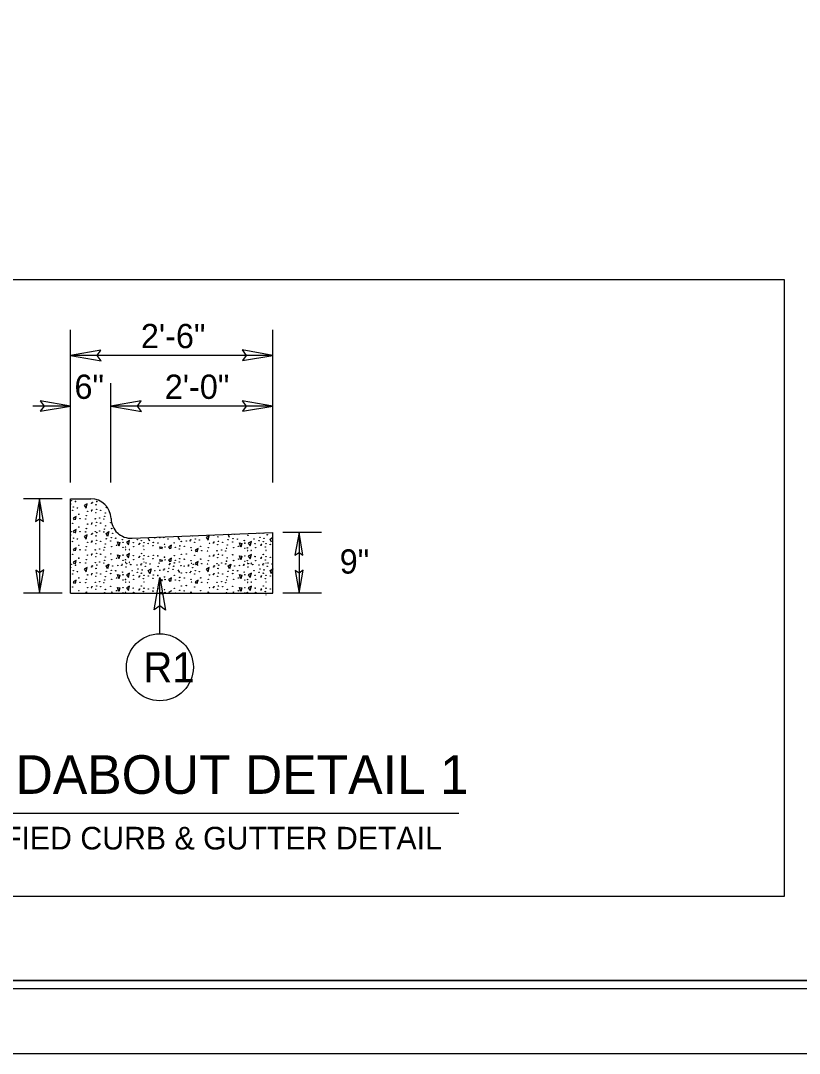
# Model space of a CAD drawing. Extents: x 1640342 to 1730599, y 538663 to 843747.
# Drawn here: x 1729959.6 to 1730007.8, y 538663.2 to 538727.1 of the extents above; entities that cross this region are included whole.
import ezdxf

# ---------------------------------------------------------------- set-up
doc = ezdxf.new("R2010")
doc.units = 0
for name, color, linetype in [('Default', 7, 'Continuous'), ('Sheet Plan CELL', 7, 'Continuous'), ('Sheet Plot Border Inside CELL', 7, 'Continuous'), ('Sheet Plot Border Outside CELL', 7, 'Continuous'), ('Typical Curb CELL', 7, 'Continuous'), ('Typical ID Circle CELL', 7, 'Continuous'), ('Typical Pavement Slope CELL', 7, 'Continuous'), ('Typical Terminator CELL', 7, 'Continuous'), ('Typical Text ID Circle CELL', 7, 'Continuous'), ('Typical Text Label CELL', 7, 'Continuous')]:
    doc.layers.add(name, color=color, linetype=linetype)

msp = doc.modelspace()

# ---------------------------------------------------------------- linework, layer by layer
at = {"layer": 'Default'}
for p, q in [((1729962.679, 538698.511), (1729962.679, 538707.96)), ((1729975.179, 538698.511), (1729975.179, 538707.96)), ((1729975.179, 538706.377), (1729962.679, 538706.377)), ((1729965.173, 538698.511), (1729965.173, 538704.667)), ((1729962.679, 538703.241), (1729960.338, 538703.241)), ((1729975.179, 538703.241), (1729965.173, 538703.241)), ((1729962.15, 538697.511), (1729959.761, 538697.511)), ((1729960.761, 538697.511), (1729960.761, 538691.677)), ((1729978.196, 538695.427), (1729975.807, 538695.427)), ((1729976.807, 538695.427), (1729976.807, 538691.677)), ((1729962.15, 538691.677), (1729959.761, 538691.677)), ((1729978.196, 538691.677), (1729975.807, 538691.677))]:
    msp.add_line(p, q, dxfattribs=at)
for points in [[(1729964.553, 538706.699), (1729962.679, 538706.377), (1729964.564, 538706.043), (1729964.324, 538706.377)], [(1729973.305, 538706.054), (1729975.179, 538706.377), (1729973.295, 538706.71), (1729973.534, 538706.377)], [(1729960.805, 538702.918), (1729962.679, 538703.241), (1729960.795, 538703.574), (1729961.034, 538703.241)], [(1729967.047, 538703.563), (1729965.173, 538703.241), (1729967.057, 538702.907), (1729966.818, 538703.241)], [(1729973.305, 538702.918), (1729975.179, 538703.241), (1729973.295, 538703.574), (1729973.534, 538703.241)], [(1729961.003, 538696.105), (1729960.761, 538697.511), (1729960.511, 538696.098), (1729960.761, 538696.277)], [(1729977.049, 538694.022), (1729976.807, 538695.427), (1729976.557, 538694.014), (1729976.807, 538694.194)], [(1729960.522, 538693.099), (1729960.764, 538691.693), (1729961.014, 538693.106), (1729960.764, 538692.927)], [(1729976.565, 538693.078), (1729976.807, 538691.672), (1729977.057, 538693.086), (1729976.807, 538692.906)]]:
    msp.add_lwpolyline(points, close=True, dxfattribs=at)
at = {"layer": 'Sheet Plan CELL'}
for points in [[(1729873.99, 538667.718), (1729873.985, 538877.713), (1730133.983, 538877.721), (1730133.985, 538847.708), (1730173.993, 538847.706), (1730173.993, 538667.718)], [(1730173.998, 538877.718), (1729873.99, 538877.718), (1729873.99, 538667.718), (1730173.993, 538667.718)]]:
    msp.add_lwpolyline(points, close=True, dxfattribs=at)
at = {"layer": 'Sheet Plot Border Inside CELL'}
msp.add_lwpolyline([(1729843.293, 538667.216), (1730176.49, 538667.218), (1730176.493, 538878.216), (1729843.293, 538878.216)], close=True, dxfattribs=at)
at = {"layer": 'Sheet Plot Border Outside CELL'}
msp.add_lwpolyline([(1729840.693, 538663.216), (1730177.393, 538663.216), (1730177.393, 538882.216), (1729840.693, 538882.216)], close=True, dxfattribs=at)
at = {"layer": 'Typical Curb CELL'}
for p, q in [((1729963.704, 538697.2), (1729963.518, 538697.097)), ((1729963.518, 538697.097), (1729963.638, 538696.929)), ((1729963.638, 538696.929), (1729963.704, 538697.2)), ((1729963.02, 538696.405), (1729962.834, 538696.303)), ((1729962.834, 538696.303), (1729962.901, 538696.209)), ((1729962.973, 538696.211), (1729963.02, 538696.405)), ((1729963.02, 538695.607), (1729962.834, 538695.505)), ((1729962.834, 538695.505), (1729962.901, 538695.411)), ((1729962.973, 538695.412), (1729963.02, 538695.607)), ((1729963.704, 538695.279), (1729963.518, 538695.177)), ((1729963.518, 538695.177), (1729963.638, 538695.009)), ((1729963.638, 538695.009), (1729963.704, 538695.279)), ((1729964.882, 538695.371), (1729965.052, 538695.492)), ((1729964.966, 538695.184), (1729964.882, 538695.371)), ((1729965.052, 538695.492), (1729964.966, 538695.184)), ((1729967.57, 538694.893), (1729967.486, 538695.079)), ((1729969.302, 538695.13), (1729969.423, 538694.962)), ((1729971.244, 538695.22), (1729971.057, 538695.118)), ((1729971.057, 538695.118), (1729971.178, 538694.95)), ((1729971.178, 538694.95), (1729971.244, 538695.22)), ((1729972.505, 538695.125), (1729972.421, 538695.312)), ((1729975.026, 538695.02), (1729975.196, 538695.141)), ((1729975.11, 538694.834), (1729975.026, 538695.02)), ((1729963.02, 538694.485), (1729962.834, 538694.382)), ((1729962.834, 538694.382), (1729962.901, 538694.289)), ((1729962.973, 538694.29), (1729963.02, 538694.485)), ((1729965.584, 538694.838), (1729965.734, 538694.809)), ((1729965.658, 538694.584), (1729965.584, 538694.838)), ((1729965.734, 538694.809), (1729965.658, 538694.584)), ((1729966.088, 538694.355), (1729966.095, 538694.355)), ((1729966.318, 538694.926), (1729966.132, 538694.824)), ((1729966.132, 538694.824), (1729966.253, 538694.656)), ((1729966.253, 538694.656), (1729966.318, 538694.926)), ((1729966.299, 538694.359), (1729966.32, 538694.36)), ((1729967.213, 538694.378), (1729967.235, 538694.379)), ((1729968.189, 538694.547), (1729968.338, 538694.518)), ((1729968.231, 538694.4), (1729968.189, 538694.547)), ((1729968.338, 538694.518), (1729968.299, 538694.401)), ((1729968.922, 538694.635), (1729968.736, 538694.532)), ((1729968.736, 538694.532), (1729968.822, 538694.412)), ((1729968.868, 538694.413), (1729968.922, 538694.635)), ((1729970.56, 538694.426), (1729970.373, 538694.323)), ((1729970.513, 538694.231), (1729970.56, 538694.426)), ((1729973.124, 538694.779), (1729973.274, 538694.75)), ((1729973.198, 538694.525), (1729973.124, 538694.779)), ((1729973.274, 538694.75), (1729973.198, 538694.525)), ((1729973.858, 538694.867), (1729973.671, 538694.765)), ((1729973.671, 538694.765), (1729973.792, 538694.597)), ((1729973.792, 538694.597), (1729973.858, 538694.867)), ((1729965.584, 538694.04), (1729965.734, 538694.011)), ((1729965.658, 538693.786), (1729965.584, 538694.04)), ((1729965.734, 538694.011), (1729965.658, 538693.786)), ((1729966.318, 538694.128), (1729966.132, 538694.026)), ((1729966.132, 538694.026), (1729966.253, 538693.858)), ((1729966.253, 538693.858), (1729966.318, 538694.128)), ((1729968.189, 538693.749), (1729968.338, 538693.72)), ((1729968.231, 538693.601), (1729968.189, 538693.749)), ((1729968.338, 538693.72), (1729968.299, 538693.603)), ((1729968.922, 538693.837), (1729968.736, 538693.734)), ((1729968.736, 538693.734), (1729968.822, 538693.614)), ((1729968.868, 538693.615), (1729968.922, 538693.837)), ((1729970.373, 538694.323), (1729970.441, 538694.229)), ((1729973.124, 538693.981), (1729973.274, 538693.952)), ((1729973.198, 538693.727), (1729973.124, 538693.981)), ((1729973.274, 538693.952), (1729973.198, 538693.727)), ((1729973.627, 538694.296), (1729973.635, 538694.296)), ((1729973.858, 538694.069), (1729973.671, 538693.966)), ((1729973.671, 538693.966), (1729973.792, 538693.798)), ((1729973.792, 538693.798), (1729973.858, 538694.069)), ((1729973.839, 538694.3), (1729973.86, 538694.301)), ((1729974.753, 538694.319), (1729974.775, 538694.32)), ((1729963.02, 538693.687), (1729962.834, 538693.584)), ((1729962.834, 538693.584), (1729962.901, 538693.49)), ((1729962.973, 538693.492), (1729963.02, 538693.687)), ((1729963.704, 538693.264), (1729963.518, 538693.161)), ((1729963.518, 538693.161), (1729963.638, 538692.993)), ((1729963.638, 538692.993), (1729963.704, 538693.264)), ((1729964.882, 538693.355), (1729965.052, 538693.476)), ((1729964.966, 538693.169), (1729964.882, 538693.355)), ((1729965.052, 538693.476), (1729964.966, 538693.169)), ((1729966.088, 538693.557), (1729966.095, 538693.557)), ((1729966.299, 538693.561), (1729966.32, 538693.562)), ((1729967.213, 538693.58), (1729967.235, 538693.581)), ((1729967.486, 538693.064), (1729967.656, 538693.185)), ((1729967.656, 538693.185), (1729967.57, 538692.877)), ((1729969.302, 538693.114), (1729969.423, 538692.946)), ((1729970.56, 538693.627), (1729970.373, 538693.525)), ((1729970.373, 538693.525), (1729970.441, 538693.431)), ((1729970.513, 538693.433), (1729970.56, 538693.627)), ((1729971.244, 538693.264), (1729971.057, 538693.161)), ((1729971.057, 538693.161), (1729971.178, 538692.993)), ((1729971.178, 538692.993), (1729971.244, 538693.264)), ((1729972.421, 538693.355), (1729972.591, 538693.476)), ((1729972.505, 538693.169), (1729972.421, 538693.355)), ((1729972.591, 538693.476), (1729972.505, 538693.169)), ((1729973.627, 538693.498), (1729973.635, 538693.498)), ((1729973.839, 538693.502), (1729973.86, 538693.503)), ((1729974.753, 538693.521), (1729974.775, 538693.522)), ((1729975.026, 538693.064), (1729975.196, 538693.185)), ((1729975.196, 538693.185), (1729975.11, 538692.877)), ((1729963.02, 538692.469), (1729962.834, 538692.367)), ((1729962.973, 538692.275), (1729963.02, 538692.469)), ((1729965.584, 538692.823), (1729965.734, 538692.794)), ((1729965.658, 538692.569), (1729965.584, 538692.823)), ((1729965.734, 538692.794), (1729965.658, 538692.569)), ((1729966.318, 538692.911), (1729966.132, 538692.808)), ((1729966.132, 538692.808), (1729966.253, 538692.64)), ((1729966.253, 538692.64), (1729966.318, 538692.911)), ((1729967.57, 538692.877), (1729967.486, 538693.064)), ((1729968.189, 538692.531), (1729968.338, 538692.502)), ((1729968.231, 538692.384), (1729968.189, 538692.531)), ((1729968.338, 538692.502), (1729968.299, 538692.386)), ((1729968.922, 538692.619), (1729968.736, 538692.517)), ((1729968.736, 538692.517), (1729968.822, 538692.396)), ((1729968.868, 538692.397), (1729968.922, 538692.619)), ((1729970.56, 538692.469), (1729970.373, 538692.367)), ((1729970.513, 538692.275), (1729970.56, 538692.469)), ((1729973.124, 538692.823), (1729973.274, 538692.794)), ((1729973.198, 538692.569), (1729973.124, 538692.823)), ((1729973.274, 538692.794), (1729973.198, 538692.569)), ((1729973.858, 538692.911), (1729973.671, 538692.808)), ((1729973.671, 538692.808), (1729973.792, 538692.64)), ((1729973.792, 538692.64), (1729973.858, 538692.911)), ((1729975.11, 538692.877), (1729975.026, 538693.064)), ((1729962.834, 538692.367), (1729962.901, 538692.273)), ((1729965.584, 538692.024), (1729965.734, 538691.996)), ((1729965.658, 538691.77), (1729965.584, 538692.024)), ((1729965.734, 538691.996), (1729965.658, 538691.77)), ((1729966.088, 538692.339), (1729966.095, 538692.34)), ((1729966.318, 538692.113), (1729966.132, 538692.01)), ((1729966.132, 538692.01), (1729966.253, 538691.842)), ((1729966.253, 538691.842), (1729966.318, 538692.113)), ((1729966.299, 538692.344), (1729966.32, 538692.344)), ((1729967.213, 538692.363), (1729967.235, 538692.363)), ((1729968.922, 538691.821), (1729968.736, 538691.719)), ((1729970.373, 538692.367), (1729970.441, 538692.273)), ((1729973.124, 538692.024), (1729973.274, 538691.996)), ((1729973.198, 538691.77), (1729973.124, 538692.024)), ((1729973.274, 538691.996), (1729973.198, 538691.77)), ((1729973.627, 538692.339), (1729973.635, 538692.34)), ((1729973.858, 538692.113), (1729973.671, 538692.01)), ((1729973.671, 538692.01), (1729973.792, 538691.842)), ((1729973.792, 538691.842), (1729973.858, 538692.113)), ((1729973.839, 538692.344), (1729973.86, 538692.344)), ((1729974.753, 538692.363), (1729974.775, 538692.363)), ((1729968.189, 538691.733), (1729968.338, 538691.704)), ((1729968.231, 538691.586), (1729968.189, 538691.733)), ((1729968.338, 538691.704), (1729968.299, 538691.587)), ((1729974.753, 538691.565), (1729974.775, 538691.565))]:
    msp.add_line(p, q, dxfattribs=at)
for centre in [(1729962.682, 538697.19), (1729962.729, 538697.395), (1729962.852, 538696.994), (1729962.982, 538697.34), (1729963.104, 538696.938), (1729963.989, 538697.235), (1729964.021, 538697.295), (1729964.255, 538697.136), (1729964.302, 538697.342), (1729964.882, 538696.954), (1729962.805, 538696.788), (1729963.188, 538696.555), (1729963.254, 538696.274), (1729963.606, 538696.261), (1729963.652, 538696.467), (1729963.729, 538696.74), (1729963.972, 538696.75), (1729964.005, 538696.81), (1729964.201, 538696.271), (1729964.239, 538696.651), (1729964.286, 538696.857), (1729964.482, 538696.318), (1729964.538, 538696.801), (1729964.734, 538696.262), (1729964.781, 538696.429), (1729964.827, 538696.635), (1729962.805, 538695.99), (1729963.188, 538695.756), (1729963.652, 538695.669), (1729963.729, 538695.942), (1729963.972, 538695.951), (1729964.005, 538696.012), (1729964.239, 538695.853), (1729964.286, 538696.059), (1729964.538, 538696.003), (1729964.781, 538695.631), (1729964.827, 538695.836), (1729965.163, 538696.025), (1729965.219, 538695.67), (1729962.682, 538695.269), (1729962.729, 538695.475), (1729962.852, 538695.074), (1729962.982, 538695.419), (1729963.104, 538695.018), (1729963.254, 538695.476), (1729963.606, 538695.463), (1729963.989, 538695.315), (1729964.021, 538695.375), (1729964.201, 538695.473), (1729964.255, 538695.216), (1729964.302, 538695.422), (1729964.482, 538695.52), (1729964.734, 538695.464), (1729964.882, 538695.034), (1729965.191, 538695.099), (1729965.284, 538695.371), (1729965.472, 538695.071), (1729965.593, 538695.399), (1729965.883, 538694.987), (1729966.8, 538694.979), (1729967.889, 538695.079), (1729968.197, 538695.107), (1729968.44, 538695.117), (1729968.707, 538695.018), (1729970.222, 538695.21), (1729970.391, 538695.015), (1729971.529, 538695.256), (1729971.795, 538695.157), (1729972.73, 538695.04), (1729972.824, 538695.312), (1729973.011, 538695.012), (1729973.643, 538695.25), (1729974.026, 538695.016), (1729974.329, 538695.37), (1729974.386, 538695.126), (1729974.572, 538695.38), (1729974.643, 538695.07), (1729974.838, 538695.281), (1729962.805, 538694.868), (1729963.188, 538694.634), (1729963.254, 538694.354), (1729963.606, 538694.34), (1729963.652, 538694.546), (1729963.729, 538694.82), (1729963.972, 538694.829), (1729964.005, 538694.89), (1729964.201, 538694.351), (1729964.239, 538694.73), (1729964.286, 538694.936), (1729964.482, 538694.397), (1729964.538, 538694.88), (1729964.734, 538694.342), (1729964.781, 538694.508), (1729964.827, 538694.714), (1729965.163, 538694.903), (1729965.219, 538694.547), (1729965.518, 538694.631), (1729965.916, 538694.823), (1729965.916, 538694.505), (1729966.075, 538694.533), (1729966.552, 538694.795), (1729966.58, 538694.543), (1729966.911, 538694.685), (1729966.944, 538694.746), (1729967.057, 538694.923), (1729967.178, 538694.586), (1729967.224, 538694.792), (1729967.486, 538694.743), (1729967.767, 538694.611), (1729967.795, 538694.808), (1729968.076, 538694.78), (1729968.487, 538694.696), (1729968.52, 538694.532), (1729969.091, 538694.784), (1729969.156, 538694.504), (1729969.404, 538694.402), (1729969.432, 538694.599), (1729969.526, 538694.87), (1729969.713, 538694.571), (1729969.835, 538694.898), (1729970.078, 538694.908), (1729970.11, 538694.968), (1729970.125, 538694.487), (1729970.345, 538694.809), (1729970.644, 538694.959), (1729970.728, 538694.575), (1729971.192, 538694.487), (1729971.269, 538694.761), (1729971.512, 538694.77), (1729971.545, 538694.83), (1729971.779, 538694.671), (1729971.825, 538694.877), (1729972.021, 538694.338), (1729972.078, 538694.821), (1729972.32, 538694.449), (1729972.367, 538694.655), (1729972.422, 538694.975), (1729972.703, 538694.844), (1729972.759, 538694.488), (1729973.058, 538694.572), (1729973.423, 538694.928), (1729973.455, 538694.764), (1729973.455, 538694.446), (1729973.614, 538694.474), (1729974.092, 538694.736), (1729974.12, 538694.483), (1729974.339, 538694.92), (1729974.451, 538694.626), (1729974.483, 538694.686), (1729974.597, 538694.864), (1729974.717, 538694.527), (1729974.764, 538694.733), (1729975.026, 538694.683), (1729962.805, 538694.07), (1729963.188, 538693.836), (1729963.652, 538693.748), (1729963.729, 538694.022), (1729963.972, 538694.031), (1729964.005, 538694.091), (1729964.239, 538693.932), (1729964.286, 538694.138), (1729964.538, 538694.082), (1729964.781, 538693.71), (1729964.827, 538693.916), (1729965.163, 538694.105), (1729965.219, 538693.749), (1729965.518, 538693.833), (1729965.916, 538694.025), (1729965.916, 538693.707), (1729966.075, 538693.735), (1729966.552, 538693.997), (1729966.58, 538693.744), (1729966.911, 538693.887), (1729966.944, 538693.947), (1729967.057, 538694.125), (1729967.178, 538693.788), (1729967.224, 538693.994), (1729967.486, 538693.944), (1729967.767, 538693.813), (1729967.795, 538694.01), (1729968.076, 538693.982), (1729968.487, 538693.898), (1729968.52, 538693.733), (1729969.091, 538693.986), (1729969.156, 538693.706), (1729969.432, 538693.801), (1729969.526, 538694.072), (1729969.713, 538693.773), (1729969.835, 538694.1), (1729970.157, 538694.322), (1729970.345, 538694.011), (1729970.728, 538693.777), (1729970.793, 538694.295), (1729971.145, 538694.281), (1729971.269, 538693.962), (1729971.512, 538693.972), (1729971.545, 538694.032), (1729971.74, 538694.292), (1729971.779, 538693.873), (1729971.825, 538694.079), (1729972.078, 538694.023), (1729972.274, 538694.282), (1729972.367, 538693.857), (1729972.703, 538694.045), (1729973.058, 538693.774), (1729973.455, 538693.966), (1729974.092, 538693.938), (1729974.451, 538693.828), (1729974.483, 538693.888), (1729974.597, 538694.066), (1729974.717, 538693.729), (1729974.764, 538693.935), (1729975.026, 538693.885), (1729962.682, 538693.254), (1729962.729, 538693.46), (1729962.982, 538693.404), (1729963.254, 538693.556), (1729963.606, 538693.542), (1729963.989, 538693.299), (1729964.021, 538693.36), (1729964.201, 538693.553), (1729964.255, 538693.2), (1729964.302, 538693.406), (1729964.482, 538693.599), (1729964.734, 538693.543), (1729965.191, 538693.084), (1729965.284, 538693.355), (1729965.593, 538693.383), (1729965.836, 538693.393), (1729965.869, 538693.453), (1729966.103, 538693.294), (1729966.15, 538693.5), (1729966.402, 538693.444), (1729966.789, 538693.414), (1729966.846, 538693.169), (1729967.032, 538693.424), (1729967.064, 538693.484), (1729967.104, 538693.113), (1729967.298, 538693.325), (1729967.345, 538693.531), (1729967.598, 538693.475), (1729967.889, 538693.064), (1729968.103, 538693.322), (1729968.15, 538693.528), (1729968.197, 538693.092), (1729968.44, 538693.101), (1729968.473, 538693.162), (1729968.754, 538693.208), (1729968.787, 538693.439), (1729968.82, 538693.499), (1729969.006, 538693.152), (1729969.054, 538693.34), (1729969.1, 538693.546), (1729969.404, 538693.604), (1729969.498, 538693.367), (1729969.712, 538693.343), (1729969.956, 538693.352), (1729969.988, 538693.413), (1729970.125, 538693.689), (1729970.157, 538693.524), (1729970.222, 538693.254), (1729970.269, 538693.46), (1729970.521, 538693.404), (1729970.793, 538693.496), (1729971.145, 538693.483), (1729971.192, 538693.689), (1729971.529, 538693.299), (1729971.561, 538693.36), (1729971.74, 538693.493), (1729971.795, 538693.2), (1729971.842, 538693.406), (1729972.021, 538693.54), (1729972.274, 538693.484), (1729972.32, 538693.651), (1729972.73, 538693.084), (1729972.759, 538693.69), (1729972.824, 538693.355), (1729973.133, 538693.383), (1729973.376, 538693.393), (1729973.408, 538693.453), (1729973.455, 538693.648), (1729973.614, 538693.676), (1729973.643, 538693.294), (1729973.689, 538693.5), (1729973.942, 538693.444), (1729974.12, 538693.685), (1729974.329, 538693.414), (1729974.386, 538693.169), (1729974.572, 538693.424), (1729974.604, 538693.484), (1729974.643, 538693.113), (1729974.838, 538693.325), (1729974.885, 538693.531), (1729975.137, 538693.475), (1729962.805, 538692.853), (1729962.852, 538693.058), (1729963.104, 538693.002), (1729963.188, 538692.619), (1729963.652, 538692.531), (1729963.729, 538692.804), (1729963.972, 538692.814), (1729964.005, 538692.874), (1729964.239, 538692.715), (1729964.286, 538692.921), (1729964.538, 538692.865), (1729964.781, 538692.493), (1729964.827, 538692.699), (1729964.882, 538693.019), (1729965.163, 538692.887), (1729965.219, 538692.532), (1729965.472, 538693.056), (1729965.518, 538692.616), (1729965.883, 538692.972), (1729965.916, 538692.808), (1729965.916, 538692.49), (1729966.075, 538692.518), (1729966.486, 538693.06), (1729966.552, 538692.78), (1729966.58, 538692.527), (1729966.8, 538692.964), (1729966.911, 538692.67), (1729966.944, 538692.73), (1729967.057, 538692.908), (1729967.178, 538692.571), (1729967.224, 538692.777), (1729967.486, 538692.727), (1729967.767, 538692.596), (1729967.795, 538692.793), (1729968.076, 538692.765), (1729968.487, 538692.68), (1729968.52, 538692.516), (1729968.707, 538693.003), (1729969.091, 538692.769), (1729969.156, 538692.488), (1729969.404, 538692.446), (1729969.432, 538692.643), (1729969.526, 538692.914), (1729969.713, 538692.615), (1729969.835, 538692.942), (1729970.078, 538692.951), (1729970.11, 538693.012), (1729970.125, 538692.53), (1729970.345, 538692.853), (1729970.391, 538693.058), (1729970.644, 538693.002), (1729970.728, 538692.619), (1729971.192, 538692.531), (1729971.269, 538692.804), (1729971.512, 538692.814), (1729971.545, 538692.874), (1729971.779, 538692.715), (1729971.825, 538692.921), (1729972.078, 538692.865), (1729972.32, 538692.493), (1729972.367, 538692.699), (1729972.422, 538693.019), (1729972.703, 538692.887), (1729972.759, 538692.532), (1729973.011, 538693.056), (1729973.058, 538692.616), (1729973.423, 538692.972), (1729973.455, 538692.808), (1729973.455, 538692.49), (1729973.614, 538692.518), (1729974.026, 538693.06), (1729974.092, 538692.78), (1729974.12, 538692.527), (1729974.339, 538692.964), (1729974.451, 538692.67), (1729974.483, 538692.73), (1729974.597, 538692.908), (1729974.717, 538692.571), (1729974.764, 538692.777), (1729975.026, 538692.727), (1729962.805, 538692.054), (1729963.188, 538691.821), (1729963.254, 538692.338), (1729963.606, 538692.325), (1729963.729, 538692.006), (1729963.972, 538692.016), (1729964.005, 538692.076), (1729964.201, 538692.335), (1729964.239, 538691.917), (1729964.286, 538692.123), (1729964.482, 538692.382), (1729964.538, 538692.067), (1729964.734, 538692.326), (1729964.827, 538691.901), (1729965.163, 538692.089), (1729965.518, 538691.818), (1729965.916, 538692.009), (1729966.552, 538691.981), (1729966.911, 538691.872), (1729966.944, 538691.932), (1729967.057, 538692.109), (1729967.224, 538691.979), (1729967.486, 538691.929), (1729967.767, 538691.798), (1729967.795, 538691.994), (1729968.076, 538691.966), (1729968.487, 538691.882), (1729969.091, 538691.971), (1729969.432, 538691.844), (1729969.526, 538692.116), (1729969.713, 538691.816), (1729969.835, 538692.144), (1729970.157, 538692.366), (1729970.345, 538692.054), (1729970.728, 538691.821), (1729970.793, 538692.338), (1729971.145, 538692.325), (1729971.269, 538692.006), (1729971.512, 538692.016), (1729971.545, 538692.076), (1729971.74, 538692.335), (1729971.779, 538691.917), (1729971.825, 538692.123), (1729972.021, 538692.382), (1729972.078, 538692.067), (1729972.274, 538692.326), (1729972.367, 538691.901), (1729972.703, 538692.089), (1729973.058, 538691.818), (1729973.455, 538692.009), (1729974.092, 538691.981), (1729974.451, 538691.872), (1729974.483, 538691.932), (1729974.597, 538692.109), (1729974.764, 538691.979), (1729975.026, 538691.929), (1729963.652, 538691.733), (1729964.781, 538691.695), (1729965.219, 538691.734), (1729965.916, 538691.691), (1729966.075, 538691.719), (1729966.58, 538691.729), (1729967.178, 538691.773), (1729968.52, 538691.718), (1729969.156, 538691.69), (1729970.125, 538691.732), (1729971.192, 538691.733), (1729972.32, 538691.695), (1729972.759, 538691.734), (1729973.455, 538691.691), (1729973.614, 538691.719), (1729974.12, 538691.729), (1729974.717, 538691.773)]:
    msp.add_circle(centre, 0.0131, dxfattribs=at)
for centre, start, end in [((1729966.091, 538694.368), 287.79478, 254.59053), ((1729966.309, 538694.368), 323.39792, 218.98739), ((1729967.224, 538694.371), 36.13839, 146.24692), ((1729973.631, 538694.308), 287.79478, 254.59053), ((1729973.849, 538694.308), 323.39792, 218.98739), ((1729974.764, 538694.312), 36.13839, 146.24692), ((1729966.091, 538693.57), 287.79478, 254.59053), ((1729966.309, 538693.57), 323.39792, 218.98739), ((1729967.224, 538693.573), 36.13839, 146.24692), ((1729973.631, 538693.51), 287.79478, 254.59053), ((1729973.849, 538693.51), 323.39792, 218.98739), ((1729974.764, 538693.514), 36.13839, 146.24692), ((1729966.091, 538692.352), 287.79478, 254.59053), ((1729966.309, 538692.352), 323.39792, 218.98739), ((1729967.224, 538692.356), 36.13839, 146.24692), ((1729973.631, 538692.352), 287.79478, 254.59053), ((1729973.849, 538692.352), 323.39792, 218.98739), ((1729974.764, 538692.356), 36.13839, 146.24692), ((1729974.764, 538691.557), 36.13839, 146.24692)]:
    msp.add_arc(centre, 0.0131, start, end, dxfattribs=at)
at = {"layer": 'Typical ID Circle CELL'}
msp.add_line((1729968.198, 538689.16), (1729968.198, 538692.645), dxfattribs=at)
msp.add_circle((1729968.199, 538687.089), 2.071, dxfattribs=at)
at = {"layer": 'Typical Pavement Slope CELL'}
for p, q in [((1729962.679, 538691.677), (1729962.679, 538697.511)), ((1729962.679, 538697.511), (1729963.929, 538697.511)), ((1729966.481, 538695.065), (1729975.179, 538695.427)), ((1729975.179, 538691.677), (1729975.179, 538695.427)), ((1729962.679, 538691.677), (1729975.179, 538691.677))]:
    msp.add_line(p, q, dxfattribs=at)
for centre, start, end in [((1729963.929, 538696.261), 1.21757, 90), ((1729966.429, 538696.314), 181.21757, 272.38499)]:
    msp.add_arc(centre, 1.25, start, end, dxfattribs=at)
at = {"layer": 'Typical Terminator CELL'}
msp.add_lwpolyline([(1729967.852, 538690.638), (1729968.198, 538692.645), (1729968.555, 538690.627), (1729968.198, 538690.883)], close=True, dxfattribs=at)
at = {"layer": 'Typical Text Label CELL'}
msp.add_line((1729949.374, 538678.076), (1729986.682, 538678.076), dxfattribs=at)
msp.add_lwpolyline([(1729933.099, 538672.934), (1730006.831, 538672.934), (1730006.831, 538711.045), (1729933.099, 538711.045)], close=True, dxfattribs=at)

# ---------------------------------------------------------------- texts
at = {"layer": 'Default'}
for s, p in [('2\'-6"', (1729967.025, 538706.823)), ('6"', (1729962.916, 538703.687)), ('2\'-0"', (1729968.504, 538703.687)), ('9"', (1729979.321, 538692.882))]:
    msp.add_text(s, height=1.5, dxfattribs=at).set_placement(p)
at = {"layer": 'Typical Text ID Circle CELL'}
msp.add_text('R1', height=1.8535, dxfattribs=at).set_placement((1729967.178, 538686.162))
at = {"layer": 'Typical Text Label CELL'}
for s, height, p in [('ROUNDABOUT DETAIL 1', 2.38712, (1729949.875, 538679.263)), ('2\'-6" MODIFIED CURB & GUTTER DETAIL', 1.4, (1729949.359, 538675.823))]:
    msp.add_text(s, height=height, dxfattribs=at).set_placement(p)

doc.saveas('drawing.dxf')
